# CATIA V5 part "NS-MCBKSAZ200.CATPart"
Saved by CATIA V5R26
Part number: NS-MCBKSAZ200
Bounding box of the stored display mesh (mm): x -120.601 to 120.601, y -249.867 to 0, z -57.2 to 55.6
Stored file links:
  R:\Document\坂尻\その他\ナベヤデータ変換\安全カバーキャスター\MCBKSAZ200\NS-MCBKSAZ200.CATPart
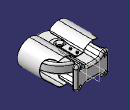
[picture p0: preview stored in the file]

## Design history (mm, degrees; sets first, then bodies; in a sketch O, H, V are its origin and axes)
Body1 (main body)
  Solid1: solid without history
